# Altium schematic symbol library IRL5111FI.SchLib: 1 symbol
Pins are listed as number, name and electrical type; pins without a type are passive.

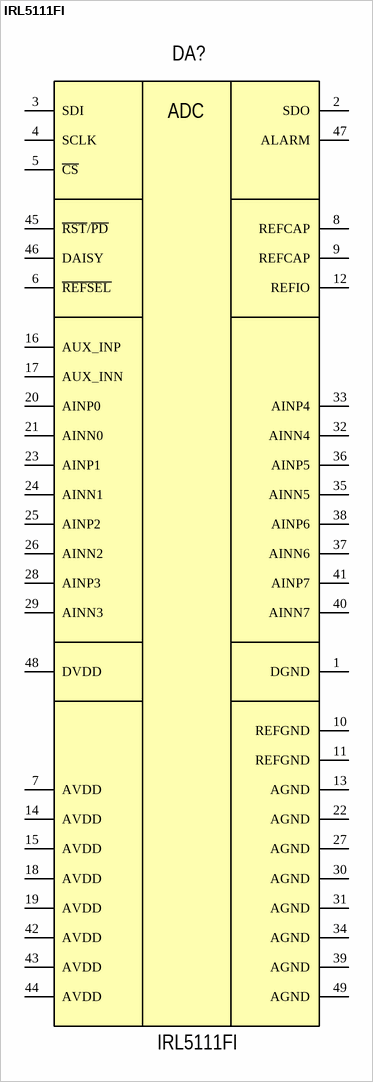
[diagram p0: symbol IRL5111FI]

## IRL5111FI
designator DA?
Микросхема 8-канального 12-битного АЦП с биполярным входным диапазоном; TemperatureOperating: - 40°C to + 85°C
pins: 1 DGND, 2 SDO, 3 SDI, 4 SCLK, 5 ~{CS}, 6 ~{REFSEL}, 7 AVDD, 8 REFCAP, 9 REFCAP, 10 REFGND, 11 REFGND, 12 REFIO, 13 AGND, 14 AVDD, 15 AVDD, 16 AUX_INP, 17 AUX_INN, 18 AVDD, 19 AVDD, 20 AINP0, 21 AINN0, 22 AGND, 23 AINP1, 24 AINN1, 25 AINP2, 26 AINN2, 27 AGND, 28 AINP3, 29 AINN3, 30 AGND, 31 AGND, 32 AINN4, 33 AINP4, 34 AGND, 35 AINN5, 36 AINP5, 37 AINN6, 38 AINP6, 39 AGND, 40 AINN7, 41 AINP7, 42 AVDD, 43 AVDD, 44 AVDD, 45 ~{RST}/~{PD}, 46 DAISY, 47 ALARM, 48 DVDD, 49 AGND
